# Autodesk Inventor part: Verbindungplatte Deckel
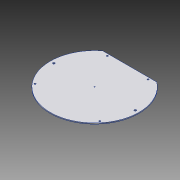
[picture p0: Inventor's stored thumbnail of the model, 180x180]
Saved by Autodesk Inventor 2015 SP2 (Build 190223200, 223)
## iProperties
Created: 2012-10
Part Number: Verbindungplatte Deckel
Material: Aluminium 6061
Document SubType Name: Modeling
Designer: rYan
Density: 2.71 g/cm^3
Mass: 51.3916 g
Surface Area: 139.478 cm^2
Volume: 18.9637 cm^3
Appearance: Aluminium - flach
Author: rYan
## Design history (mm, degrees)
sketch "Skizze1"
  geometry: L1 (0, 100.2)-(0, -118.2) reference; L2 (-121.8, 0)-(121.8, 0) reference; L3 (-52.991, 69)-(-32.512, 69); L4 (32.512, 69)-(52.991, 69); L5 (-32.512, 69)-(32.512, 69); C1 r 1 at (0, 0); A1 r 87 centre (0, 0) between (-52.991, 69) and (52.991, 69); 1 further point
  constraints: 6 end point, 2 centre point, 2 coincident, 2 parallel, 2 point on circle
  dimensions: "d0" = 174 diameter of A1; "d166" = 69 distance between parallel lines of L2 L5; "d200" = 2 diameter of C1
extrude "Extrusion1" new body sketch "Skizze1" stored distance "d6" = 2 (= d200); taper "d7" = 0 deg
sketch "Skizze10" dims "d77" = 166
  geometry: L1 (52.991, 69)-(-52.991, 69) reference; L2 (0, 0)-(63.582, -53.351); L3 (-121.8, 0)-(121.8, 0) reference; L4 (0, 69)-(0, 61); L5 (-40, 65)-(40, 65); A1 r 87 centre (0, 0) between (-52.991, 69) and (52.991, 69) reference; 2 further points
  constraints: 6 end point, 3 coincident, 1 midpoint, 1 perpendicular, 1 symmetric about line, 3 other
  dimensions: "d80" = 40 deg angle of L3 L2; "d82" = 80 distance of L5.start L5.end; "d125" = 65 distance between parallel lines of L3 L5
hole "Bohrung6" sketch "Skizze10" diameter "d83" = 3.2; stored, may be unused: countersink angle "d87" = 90 deg, drill point angle "d89" = 118 deg; dims "d84" = 6, "d85" = 4, "d86" = 2, "d88" = 8.8
mirror "Spiegeln3"
sketch "Skizze23"
  geometry: L1 (-121.8, 0)-(121.8, 0); L2 (0, 100.2)-(0, -118.2); L3 (-80, 0)-(80, 0); 3 further points
  constraints: 6 end point, 2 coincident, 2 point on line, 1 symmetric about line
  dimensions: "d167" = 160 distance of L3.start L3.end
hole "Bohrung12" sketch "Skizze23" at (-80, 0), (80, 0) diameter "d168" = 4.2; stored, may be unused: countersink angle "d172" = 90 deg, drill point angle "d174" = 118 deg; dims "d169" = 6, "d170" = 10, "d171" = 3, "d173" = 12
workaxis "Arbeitsachse2"
node "Volumenkörper1"
other parameters: "d2" = 8, "d3" = 72, "d78" = 40 deg
